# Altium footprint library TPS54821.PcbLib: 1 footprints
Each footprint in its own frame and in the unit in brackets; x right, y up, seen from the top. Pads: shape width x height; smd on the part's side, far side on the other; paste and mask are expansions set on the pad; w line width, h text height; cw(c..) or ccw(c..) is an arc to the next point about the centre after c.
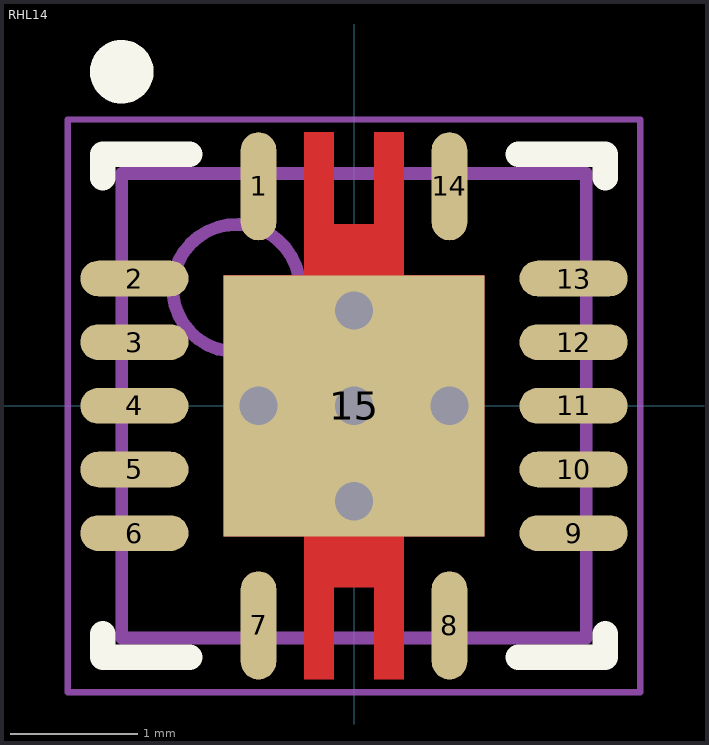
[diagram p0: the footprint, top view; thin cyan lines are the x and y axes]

## RHL14 [mm]
pads (15):
  oval 0.28x0.85 smd paste-0.025 mask+0.07: 1(-0.75,1.725) 7(-0.75,-1.725) 8(0.75,-1.725) 14(0.75,1.725)
  oval 0.85x0.28 smd paste-0.025 mask+0.07: 2(-1.725,1) 3(-1.725,0.5) 4(-1.725,0) 5(-1.725,-0.5) 6(-1.725,-1) 9(1.725,-1) 10(1.725,-0.5) 11(1.725,0) 12(1.725,0.5) 13(1.725,1)
  rect 2.05x2.05 smd paste-2 mask+0.05: 15(0,0)
via 0,0 diameter 0.5 hole 0.3
via -0.75,0 diameter 0.5 hole 0.3
via 0.75,0 diameter 0.5 hole 0.3
via 0,0.75 diameter 0.5 hole 0.3
via 0,-0.75 diameter 0.5 hole 0.3
Top Layer:
  region: 0.39,2.15 0.16,2.15 0.16,1.425 -0.16,1.425 -0.16,2.15 -0.39,2.15 -0.39,1.025 -1.025,1.025 -1.025,-1.025 -0.39,-1.025 -0.39,-2.15 -0.16,-2.15 -0.16,-1.425 0.16,-1.425 0.16,-2.15 0.39,-2.15 0.39,-1.025 1.025,-1.025 1.025,1.025 0.39,1.025
Top Overlay:
  circle w0.25: c-1.825,2.625 r0.125
  lines w0.2: -1.975,-1.79 -1.975,-1.975 -1.29,-1.975 ; -1.975,1.79 -1.975,1.975 -1.29,1.975 ; 1.29,-1.975 1.975,-1.975 1.975,-1.79 ; 1.29,1.975 1.975,1.975 1.975,1.79
Top Paste:
  region: -0.16,-2.15 -0.16,-1.25 -0.39,-1.25 -0.39,-2.15
  region: -0.39,2.15 -0.39,1.25 -0.16,1.25 -0.16,2.15
  region: 0.16,2.15 0.16,1.25 0.39,1.25 0.39,2.15
  region: -0.97,0.97 -0.97,0.15 -0.15,0.15 -0.15,0.97
  region: 0.97,0.15 0.97,0.97 0.15,0.97 0.15,0.15
  region: 0.39,-2.15 0.39,-1.25 0.16,-1.25 0.16,-2.15
  region: 0.97,-0.97 0.97,-0.15 0.15,-0.15 0.15,-0.97
  region: -0.97,-0.15 -0.97,-0.97 -0.15,-0.97 -0.15,-0.15
Mechanical 13:
  circle w0.1: c-0.925,0.925 r0.5
  lines w0.1: -1.825,-1.825 -1.825,1.825 1.825,1.825 1.825,-1.825 -1.825,-1.825
Mechanical 15:
  lines w0.05: -2.25,-2.25 -2.25,2.25 2.25,2.25 2.25,-2.25 -2.25,-2.25
  lines w0.1: -0.5,0 0.5,0 ; 0,-0.5 0,0.5
3D body "RHL0014A.stp": height 1, standoff 0, extent -1.75,-1.75 1.75,1.75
